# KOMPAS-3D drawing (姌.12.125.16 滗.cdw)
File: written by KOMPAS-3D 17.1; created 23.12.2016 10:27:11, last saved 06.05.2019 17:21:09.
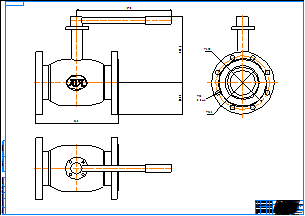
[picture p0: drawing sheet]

Sheet 1: A0, landscape

Title block, sheet 1: name: КШ.12.125.16 фф; material: Внимание! Данный продукт является объектом авторского права ООО «Торговый Дом АДЛ». / Запрещается изменение, копирование, распространение / (в том числе путем копирования на другие сайты и ресурсы в Интернете) / или любое иное использование информации и объектов без предварительного / согласия правообладателя (ООО «Торговый Дом АДЛ»).; sheets: 1; organisation: ООО "Торговый дом АДЛ"; sheet format: A0; stored path: C:\Users\tra\Desktop\2д чертежи\Шаровые краны БИВАЛ\КШ_Бивал_серия_11_12\KOMPAS_2D\КШ.12.125.16 фф.cdw

Views: Вид 1, Проекционный вид 2, Проекционный вид 3
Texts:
  Klimkovich
  ADL
Dimensions and other numbers on the sheet: 325; 370; 258,4; 122,5; 210; 123; 18; 8 Отв.; 1:1; 1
